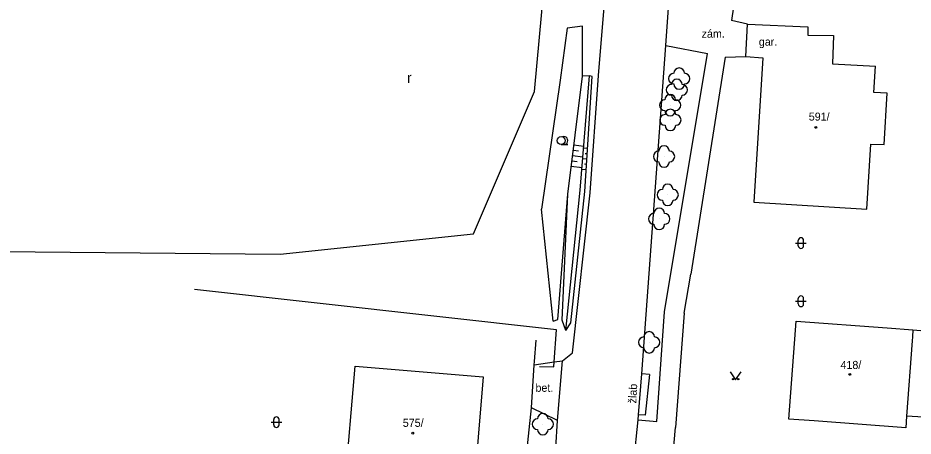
# Model space of a CAD drawing. Extents: x -737488 to -734267, y -1145775 to -1142573.
# Drawn here: x -736723.4 to -736639.5, y -1144493.7 to -1144454.6 of the extents above; entities that cross this region are included whole.
import ezdxf

# ---------------------------------------------------------------- set-up
doc = ezdxf.new("R2010")
doc.units = 0
for name, color, linetype in [('Vrstva 1', 7, 'Continuous'), ('Vrstva 10', 7, 'Continuous'), ('Vrstva 11', 7, 'Continuous'), ('Vrstva 12', 7, 'Continuous'), ('Vrstva 14', 7, 'Continuous'), ('Vrstva 3', 7, 'Continuous'), ('Vrstva 4', 7, 'Continuous'), ('Vrstva 5', 7, 'Continuous'), ('Vrstva 6', 7, 'Continuous'), ('Vrstva 8', 7, 'Continuous'), ('Vrstva 9', 7, 'Continuous')]:
    doc.layers.add(name, color=color, linetype=linetype)

# ---------------------------------------------------------------- blocks, each defined once
blk = doc.blocks.new('3.130')
at = {"layer": 'Vrstva 1'}
blk.add_circle((0, 0), 0.001, dxfattribs=at)
for centre, start, end in [((0, 1), 0, 180), ((-1, 0), 90, 270), ((1, 0), 270, 90), ((0, -1), 180, 360)]:
    blk.add_arc(centre, 1, start, end, dxfattribs=at)
blk = doc.blocks.new('3.019')
at = {"layer": 'Vrstva 1'}
blk.add_text('r', height=2, dxfattribs=at).set_placement((-0.496, -0.964))
blk = doc.blocks.new('3.110')
at = {"layer": 'Vrstva 1'}
blk.add_line((0, -0.75), (1.25, -0.75), dxfattribs=at)
blk.add_circle((0, 0), 0.75, dxfattribs=at)
blk.add_arc((0.5, 0), 0.75, 249.4944, 109.0474, dxfattribs=at)
blk = doc.blocks.new('3.140')
at = {"layer": 'Vrstva 1'}
blk.add_lwpolyline([(-1, 1.5), (0, 0), (1, 1.5)], dxfattribs=at)
for centre in [(-0.5, 0.1), (0.5, 0.1)]:
    blk.add_circle(centre, 0.1, dxfattribs=at)
blk = doc.blocks.new('3.160')
at = {"layer": 'Vrstva 1'}
for p, q in [((-1, 0), (1, 0)), ((-0.5, -0.5), (-0.5, 0.5)), ((0.5, -0.5), (0.5, 0.5))]:
    blk.add_line(p, q, dxfattribs=at)
for centre, start, end in [((0, 0.5), 0, 180), ((0, -0.5), 180, 360)]:
    blk.add_arc(centre, 0.5, start, end, dxfattribs=at)
blk = doc.blocks.new('4.020')
at = {"layer": 'Vrstva 1'}
blk.add_circle((0, 0), 0.175, dxfattribs=at)

msp = doc.modelspace()

# ---------------------------------------------------------------- linework, layer by layer
at = {"layer": 'Vrstva 10'}
for points in [[(-736669.01, -1144459.94), (-736666.86, -1144433.96)], [(-736662.69, -1144457.14), (-736662.45, -1144453.61)], [(-736664.94, -1144487.85), (-736662.69, -1144457.14)], [(-736662.69, -1144457.14), (-736658.8, -1144457.87)], [(-736663.53, -1144492.32), (-736662.82, -1144482.05), (-736658.8, -1144457.87)], [(-736671.45, -1144485.88), (-736669.77, -1144470.92), (-736669.01, -1144459.94)], [(-736672.38, -1144486.63), (-736671.45, -1144485.88)], [(-736675.02, -1144487.01), (-736673.16, -1144486.74), (-736672.38, -1144486.63)], [(-736672.83, -1144492.24), (-736672.38, -1144486.63)], [(-736665.29, -1144492.16), (-736665.25, -1144491.71), (-736664.94, -1144487.85)], [(-736664.23, -1144487.93), (-736664.94, -1144487.85)], [(-736664.23, -1144487.93), (-736664.64, -1144491.73)], [(-736672.83, -1144492.24), (-736675.27, -1144491.03)], [(-736664.64, -1144491.73), (-736665.25, -1144491.71)], [(-736673, -1144494.78), (-736672.83, -1144492.24)], [(-736665.68, -1144496.09), (-736665.29, -1144492.16)], [(-736665.29, -1144492.16), (-736663.53, -1144492.32)]]:
    msp.add_lwpolyline(points, dxfattribs=at)
at = {"layer": 'Vrstva 11'}
for points in [[(-736674.99, -1144461.43), (-736672.55, -1144434.98)], [(-736671.93, -1144455.51), (-736672.6, -1144460.38)], [(-736670.5, -1144455.31), (-736671.93, -1144455.51)], [(-736670.49, -1144460), (-736670.5, -1144455.31)], [(-736672.6, -1144460.38), (-736674.35, -1144472.45)], [(-736671.88, -1144471.03), (-736670.49, -1144460)], [(-736680.72, -1144474.77), (-736674.99, -1144461.43)], [(-736672.81, -1144482.77), (-736671.88, -1144471.03)], [(-736673.24, -1144482.92), (-736674.35, -1144472.45)], [(-736698.82, -1144476.67), (-736680.72, -1144474.77)], [(-736751.36, -1144476.15), (-736698.82, -1144476.67)], [(-736673.24, -1144482.92), (-736672.81, -1144482.77)]]:
    msp.add_lwpolyline(points, dxfattribs=at)
at = {"layer": 'Vrstva 12'}
for points in [[(-736670.72, -1144470.67), (-736669.84, -1144459.97)], [(-736669.84, -1144459.97), (-736670.49, -1144460)], [(-736670.28, -1144470.8), (-736669.58, -1144460.03)], [(-736669.58, -1144460.03), (-736669.84, -1144459.97)], [(-736671.3, -1144466.43), (-736670.38, -1144466.55)], [(-736671.43, -1144467.42), (-736670.46, -1144467.55)], [(-736671.36, -1144466.93), (-736670.89, -1144466.99)], [(-736670.02, -1144466.77), (-736670.4, -1144466.74)], [(-736670.05, -1144467.27), (-736670.24, -1144467.26)], [(-736671.49, -1144467.92), (-736671, -1144467.98)], [(-736670.08, -1144467.77), (-736670.48, -1144467.74)], [(-736670.12, -1144468.27), (-736670.32, -1144468.25)], [(-736671.55, -1144468.42), (-736670.54, -1144468.54)], [(-736670.15, -1144468.76), (-736670.56, -1144468.74)], [(-736672.05, -1144483.8), (-736670.72, -1144470.67)], [(-736671.6, -1144483.08), (-736670.28, -1144470.8)], [(-736672.4, -1144482.84), (-736671.88, -1144471.03)], [(-736672.05, -1144483.8), (-736672.4, -1144482.84)], [(-736672.05, -1144483.8), (-736671.6, -1144483.08)]]:
    msp.add_lwpolyline(points, dxfattribs=at)
at = {"layer": 'Vrstva 4'}
msp.add_lwpolyline([(-736655.21, -1144458.16), (-736655.03, -1144455.13)], dxfattribs=at)
at = {"layer": 'Vrstva 5'}
for points in [[(-736655.03, -1144455.13), (-736649.39, -1144455.37), (-736649.39, -1144456.17), (-736646.97, -1144456.2), (-736647.09, -1144458.85), (-736643.04, -1144459.07)], [(-736655.21, -1144458.16), (-736653.6, -1144458.3), (-736654.46, -1144471.78), (-736643.86, -1144472.45), (-736643.48, -1144466.38), (-736642.25, -1144466.41), (-736641.97, -1144461.58), (-736643.2, -1144461.52), (-736643.04, -1144459.07)], [(-736650.54, -1144483.77), (-736650.48, -1144482.92)], [(-736650.48, -1144482.92), (-736641.96, -1144483.55)], [(-736651.16, -1144492.09), (-736650.54, -1144483.77)], [(-736641.96, -1144483.55), (-736639.54, -1144483.73)], [(-736639.54, -1144483.73), (-736628.12, -1144484.68), (-736628.39, -1144485.85), (-736627.22, -1144485.9), (-736627.31, -1144488.2), (-736629.07, -1144488.16), (-736629.3, -1144492.45), (-736630.51, -1144492.38), (-736640.14, -1144491.82)], [(-736639.54, -1144483.73), (-736639.59, -1144484.41)], [(-736639.62, -1144484.77), (-736640.14, -1144491.82)], [(-736639.59, -1144484.41), (-736639.62, -1144484.77)], [(-736692.76, -1144498.42), (-736691.81, -1144487.13)], [(-736691.81, -1144487.13), (-736679.8, -1144488.14)], [(-736679.8, -1144488.14), (-736680.75, -1144499.43)], [(-736640.14, -1144491.82), (-736640.22, -1144492.9)], [(-736648.81, -1144492.26), (-736651.16, -1144492.09)], [(-736640.22, -1144492.9), (-736648.81, -1144492.26)]]:
    msp.add_lwpolyline(points, dxfattribs=at)
at = {"layer": 'Vrstva 9'}
for points in [[(-736653.81, -1144436.25), (-736656.55, -1144454.78)], [(-736655.03, -1144455.13), (-736656.55, -1144454.78)], [(-736657.12, -1144458.22), (-736660.34, -1144478.52)], [(-736657.12, -1144458.22), (-736655.21, -1144458.16)], [(-736660.96, -1144482.17), (-736660.34, -1144478.52)], [(-736672.95, -1144483.73), (-736706.85, -1144479.98)], [(-736660.96, -1144482.17), (-736661.79, -1144492.89)], [(-736673.19, -1144487.19), (-736673.16, -1144486.74), (-736672.95, -1144483.73)], [(-736675, -1144486.69), (-736674.83, -1144484.7)], [(-736675.02, -1144487.01), (-736675, -1144486.69)], [(-736675.27, -1144491.03), (-736675.02, -1144487.01)], [(-736674.54, -1144487.16), (-736673.19, -1144487.19)], [(-736677.16, -1144508.7), (-736675.27, -1144491.03)], [(-736662.1, -1144496.4), (-736661.79, -1144492.89)]]:
    msp.add_lwpolyline(points, dxfattribs=at)

# ---------------------------------------------------------------- block references
at = {"layer": 'Vrstva 11', "xscale": 0.5, "yscale": 0.5}
for p in [(-736661.44, -1144460.23), (-736661.66, -1144461.28), (-736662.29, -1144462.71), (-736662.27, -1144464.1), (-736662.86, -1144467.52), (-736662.52, -1144471.11), (-736663.31, -1144473.36), (-736664.25, -1144484.91), (-736674.22, -1144492.57)]:
    msp.add_blockref('3.130', p, dxfattribs=at)
at = {"layer": 'Vrstva 3', "xscale": 0.5, "yscale": 0.5}
for name, p in [('3.019', (-736686.7, -1144460.17)), ('3.110', (-736672.5, -1144466.03)), ('3.160', (-736650.03, -1144475.62)), ('3.160', (-736650.03, -1144481.07)), ('3.140', (-736656.15, -1144488.41)), ('3.160', (-736699.18, -1144492.38))]:
    msp.add_blockref(name, p, dxfattribs=at)
at = {"layer": 'Vrstva 8', "xscale": 0.5, "yscale": 0.5}
for p in [(-736648.63, -1144464.79), (-736645.46, -1144487.91), (-736686.41, -1144493.42)]:
    msp.add_blockref('4.020', p, dxfattribs=at)

# ---------------------------------------------------------------- texts
at = {"layer": 'Vrstva 14'}
for s, p in [('zám.', (-736659.34, -1144456.4)), ('gar.', (-736653.98, -1144457.15)), ('bet.', (-736674.91, -1144489.54))]:
    msp.add_text(s, height=0.75, dxfattribs=at).set_placement(p)
msp.add_text('žlab', height=0.75, rotation=86.864, dxfattribs=at).set_placement((-736665.47, -1144490.64))
at = {"layer": 'Vrstva 6'}
for s, p in [('591/', (-736649.3, -1144464.16)), ('418/', (-736646.33, -1144487.4)), ('575/', (-736687.34, -1144492.82))]:
    msp.add_text(s, height=0.75, dxfattribs=at).set_placement(p)

doc.saveas('drawing.dxf')
